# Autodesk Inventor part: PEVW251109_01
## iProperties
Created: 2009-11
Part Number: PEVW251109_01
Cost Center: 0 kg
Material: 1.0037 St 37-2
Document SubType Name: Modellieren
Designer: Student_TAB
Authority: 0 mm^3
Density: 7.85 g/cm^3
Author: Student_TAB
SaveDate: 2007-07-03
SaveTime: 10:26
TotalMass: 0 kg
TotalVolume: 0 mm^3
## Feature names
1. Sweeping1
2. Spiegeln1 [Mirror]
3. Extrusion1
